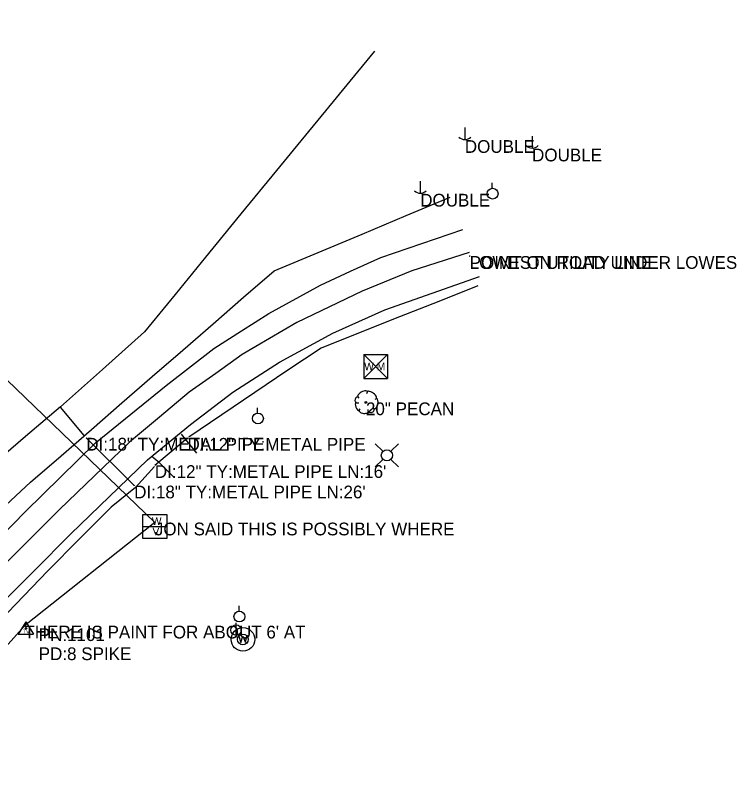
# Model space of a CAD drawing. Extents: x 1404740 to 1407214, y 1837339 to 1847120.
# Drawn here: x 1405945.4 to 1406228.7, y 1842443.8 to 1842749.5 of the extents above; entities that cross this region are included whole.
import ezdxf

# ---------------------------------------------------------------- set-up
doc = ezdxf.new("R2010")
doc.units = 0
for name, color, linetype in [('Ex_Major Contours', 7, 'Continuous'), ('S_DITCHLINE', 7, 'Continuous'), ('S_DRG_PT_SYM', 7, 'Continuous'), ('S_DRIVEWAY', 7, 'Continuous'), ('S_EDGE_PAVEMENT', 7, 'Continuous'), ('S_ELECTRIC_UTILITIES_ANNOT', 7, 'Continuous'), ('S_PAVEMENT_CROWN', 7, 'Continuous'), ('S_RDW_PT_SYM', 7, 'Continuous'), ('S_SIDE_DRAIN_ANNOT', 7, 'Continuous'), ('S_STREAM', 7, 'Continuous'), ('S_SURVEY_TEXT_ANNOT', 7, 'Continuous'), ('S_TREE', 7, 'Continuous'), ('S_TREE_ANNOT', 7, 'Continuous'), ('S_UTILITY_POLE', 7, 'Continuous'), ('S_UTILITY_POLE_ANNOT', 7, 'Continuous'), ('S_UTL_PT_SYM', 7, 'Continuous'), ('S_WATER_UTILITIES', 7, 'Continuous'), ('S_WATER_UTILITIES_ANNOT', 7, 'Continuous')]:
    doc.layers.add(name, color=color, linetype=linetype)

msp = doc.modelspace()

# ---------------------------------------------------------------- linework, layer by layer
at = {"layer": 'Ex_Major Contours'}
for p, q in [((1405991.98, 1842564.79), (1405973.17, 1842583.57)), ((1406000.11, 1842572.82), (1406012.93, 1842583.52))]:
    msp.add_line(p, q, dxfattribs=at)
at = {"layer": 'S_DITCHLINE'}
for points in [[(1406127.1, 1842643.3), (1406111.68, 1842637.19), (1406096.26, 1842631.07), (1406080.84, 1842624.96), (1406065.42, 1842618.85), (1406052.42, 1842610.1), (1406039.43, 1842601.35), (1406026.44, 1842592.61), (1406013.45, 1842583.86)], [(1405962.96, 1842595.61), (1405972.26, 1842584.46)], [(1406000.03, 1842572.3), (1405992.55, 1842564.07), (1405982.99, 1842556.38), (1405970.55, 1842543.87), (1405958.1, 1842531.36), (1405942.39, 1842514.95), (1405926.67, 1842498.54), (1405910.95, 1842482.13), (1405895.24, 1842465.71), (1405881.86, 1842451.53), (1405868.49, 1842437.35)]]:
    msp.add_lwpolyline(points, dxfattribs=at)
at = {"layer": 'S_DRG_PT_SYM'}
for points in [[(1405973.17, 1842583.57), (1405973.17, 1842583.62), (1405973.17, 1842583.57), (1405973.12, 1842583.57), (1405973.17, 1842583.57), (1405973.17, 1842583.52), (1405973.17, 1842583.57), (1405973.22, 1842583.57)], [(1406012.93, 1842583.52), (1406012.93, 1842583.57), (1406012.93, 1842583.52), (1406012.88, 1842583.52), (1406012.93, 1842583.52), (1406012.93, 1842583.47), (1406012.93, 1842583.52), (1406012.98, 1842583.52)], [(1406000.11, 1842572.82), (1406000.11, 1842572.87), (1406000.11, 1842572.82), (1406000.06, 1842572.82), (1406000.11, 1842572.82), (1406000.11, 1842572.77), (1406000.11, 1842572.82), (1406000.16, 1842572.82)], [(1405991.98, 1842564.79), (1405991.98, 1842564.84), (1405991.98, 1842564.79), (1405991.93, 1842564.79), (1405991.98, 1842564.79), (1405991.98, 1842564.74), (1405991.98, 1842564.79), (1405992.03, 1842564.79)]]:
    msp.add_lwpolyline(points, dxfattribs=at)
at = {"layer": 'S_DRIVEWAY'}
for p, q in [((1405949.47, 1842511.32), (1405946.46, 1842506.37)), ((1405949.47, 1842511.32), (1405952.42, 1842506.37)), ((1405946.46, 1842506.37), (1405952.42, 1842506.37))]:
    msp.add_line(p, q, dxfattribs=at)
for points in [[(1406010.41, 1842584.99), (1406012.18, 1842582.89), (1406016.54, 1842577.5)], [(1406007.64, 1842567.95), (1406001.75, 1842573.91), (1405999.22, 1842576.01)]]:
    msp.add_lwpolyline(points, dxfattribs=at)
for radius in [0.311, 0.183, 0.103]:
    msp.add_circle((1405949.47, 1842508.71), radius, dxfattribs=at)
at = {"layer": 'S_EDGE_PAVEMENT'}
for points in [[(1405825.85, 1842428.4), (1405841.19, 1842444.82), (1405850.15, 1842452.84), (1405856.44, 1842459.74), (1405871.87, 1842475.5), (1405887.3, 1842491.25), (1405903.15, 1842507.49), (1405919, 1842523.72), (1405934.15, 1842539.16), (1405949.29, 1842554.61), (1405963.06, 1842568.1), (1405976.82, 1842581.59), (1405990.68, 1842592.85), (1406004.54, 1842604.12), (1406023.33, 1842618.72), (1406034.11, 1842625.59), (1406044.9, 1842632.46), (1406065.21, 1842643.59), (1406077.05, 1842649.02), (1406088.89, 1842654.45), (1406104.99, 1842659.96), (1406121.09, 1842665.48)], [(1405864, 1842439.51), (1405878.64, 1842455.29), (1405893.11, 1842470.34), (1405907.58, 1842485.4), (1405922.75, 1842501), (1405937.92, 1842516.6), (1405952.51, 1842531.2), (1405967.11, 1842545.81), (1405982.2, 1842560.34), (1405997.29, 1842574.86), (1406014.16, 1842588.82), (1406030.8, 1842601.55), (1406049.08, 1842613.36), (1406070.04, 1842624.69), (1406090.47, 1842633.85), (1406109.07, 1842640.4), (1406127.67, 1842646.95)]]:
    msp.add_lwpolyline(points, dxfattribs=at)
at = {"layer": 'S_PAVEMENT_CROWN'}
msp.add_lwpolyline([(1406123.66, 1842656.34), (1406101.17, 1842649.25), (1406081.53, 1842641.18), (1406068.7, 1842635.01), (1406055.87, 1842628.84), (1406034.44, 1842616.3), (1406024.05, 1842608.9), (1406013.66, 1842601.51), (1406001.88, 1842591.71), (1405990.1, 1842581.9), (1405976.37, 1842568.67), (1405962.64, 1842555.44), (1405947.87, 1842540.59), (1405933.09, 1842525.75), (1405918.78, 1842510.91), (1405904.46, 1842496.07), (1405890.02, 1842480.85), (1405875.57, 1842465.64), (1405861.34, 1842450.66), (1405847.12, 1842435.69)], dxfattribs=at)
at = {"layer": 'S_RDW_PT_SYM'}
msp.add_lwpolyline([(1406123.85, 1842654.98), (1406123.85, 1842655.03), (1406123.85, 1842654.98), (1406123.8, 1842654.98), (1406123.85, 1842654.98), (1406123.85, 1842654.93), (1406123.85, 1842654.98), (1406123.9, 1842654.98)], dxfattribs=at)
at = {"layer": 'S_STREAM'}
msp.add_lwpolyline([(1406086.45, 1842735.46), (1406076.8, 1842723.75), (1406067.15, 1842712.04), (1406057.5, 1842700.33), (1406047.86, 1842688.62), (1406033.92, 1842671.61), (1406019.99, 1842654.6), (1406008.04, 1842639.91), (1405996.1, 1842625.22), (1405979.54, 1842610.47), (1405962.98, 1842595.73), (1405949.29, 1842584.1), (1405935.6, 1842572.46)], dxfattribs=at)
at = {"layer": 'S_TREE'}
for p, q in [((1406079.83, 1842599.7), (1406080.33, 1842599.12)), ((1406083.62, 1842601.72), (1406083.24, 1842600.86)), ((1406079.17, 1842597.38), (1406080.29, 1842597.38)), ((1406087.19, 1842598.93), (1406086.53, 1842598.66)), ((1406080.33, 1842594.2), (1406080.8, 1842594.9)), ((1406084.01, 1842593.93), (1406083.93, 1842594.7)), ((1406086.41, 1842594.82), (1406085.95, 1842595.25))]:
    msp.add_line(p, q, dxfattribs=at)
msp.add_lwpolyline([(1405941.54, 1842557.14), (1405951.29, 1842566.15), (1405963.25, 1842576.52), (1405975.21, 1842586.9), (1405987.17, 1842597.28), (1405999.12, 1842607.66), (1406011.08, 1842618.04), (1406023.04, 1842628.41), (1406035, 1842638.79), (1406046.96, 1842649.17), (1406064.27, 1842656.41), (1406081.58, 1842663.65), (1406098.9, 1842670.89), (1406116.21, 1842678.12)], dxfattribs=at)
msp.add_circle((1406083.07, 1842597.47), 0.341, dxfattribs=at)
for centre, major_axis, ratio, start_param, end_param in [((1406081.73, 1842600.67), (1.86, 1.08), 0.471018, 0, 3.141593), ((1406085.39, 1842600.35), (-1.81, 1.36), 0.405113, 3.141593, 6.283186), ((1406079.5, 1842598.56), (0.31, 1.03), 0.646762, 0, 3.141593), ((1406086.74, 1842596.94), (0.46, 2.04), 0.482994, 3.141593, 6.283185), ((1406079.8, 1842595.91), (-0.61, 1.6), 0.420543, 6.283185, 9.424777), ((1406082.26, 1842594.13), (-1.83, 0.19), 0.529943, 0, 3.141593), ((1406085.22, 1842594.42), (1.09, 0.46), 0.711534, 3.141592, 6.283185)]:
    msp.add_ellipse(centre, major_axis=major_axis, ratio=ratio, start_param=start_param, end_param=end_param, dxfattribs=at)
at = {"layer": 'S_UTILITY_POLE'}
for p, q in [((1406121.91, 1842705.5), (1406121.91, 1842700.77)), ((1406148.33, 1842702.16), (1406148.33, 1842697.43)), ((1406104.39, 1842684.4), (1406104.39, 1842679.67)), ((1406132.71, 1842681.66), (1406132.71, 1842683.77)), ((1406040.5, 1842593.31), (1406040.5, 1842595.42)), ((1406089.69, 1842578.27), (1406086.71, 1842581.25)), ((1406092.87, 1842578.27), (1406095.85, 1842581.25)), ((1406089.69, 1842575.09), (1406086.71, 1842572.11)), ((1406092.87, 1842575.09), (1406095.85, 1842572.11)), ((1406033.2, 1842515.47), (1406033.2, 1842517.58)), ((1406032.05, 1842505.08), (1406032.05, 1842510.87))]:
    msp.add_line(p, q, dxfattribs=at)
for centre, radius in [((1406132.84, 1842679.52), 2.13), ((1406040.62, 1842591.17), 2.13), ((1406091.29, 1842576.69), 2.21), ((1406033.33, 1842513.33), 2.13), ((1406032.05, 1842508.01), 2.05)]:
    msp.add_circle(centre, radius, dxfattribs=at)
for centre in [(1406121.97, 1842704.2), (1406148.4, 1842700.86), (1406104.45, 1842683.1)]:
    msp.add_arc(centre, 3.41, 226.3972, 313.6028, dxfattribs=at)
at = {"layer": 'S_UTL_PT_SYM'}
for points in [[(1406123.85, 1842654.98), (1406123.85, 1842655.03), (1406123.85, 1842654.98), (1406123.8, 1842654.98), (1406123.85, 1842654.98), (1406123.85, 1842654.93), (1406123.85, 1842654.98), (1406123.9, 1842654.98)], [(1406000.11, 1842550.24), (1406000.11, 1842550.29), (1406000.11, 1842550.24), (1406000.06, 1842550.24), (1406000.11, 1842550.24), (1406000.11, 1842550.19), (1406000.11, 1842550.24), (1406000.16, 1842550.24)], [(1405948.84, 1842509.73), (1405948.84, 1842509.78), (1405948.84, 1842509.73), (1405948.79, 1842509.73), (1405948.84, 1842509.73), (1405948.84, 1842509.68), (1405948.84, 1842509.73), (1405948.89, 1842509.73)]]:
    msp.add_lwpolyline(points, dxfattribs=at)
at = {"layer": 'S_WATER_UTILITIES'}
for p, q in [((1405793.44, 1842749.52), (1406000.11, 1842550.24)), ((1406082.2, 1842616.34), (1406091.54, 1842616.34)), ((1406082.2, 1842616.34), (1406082.2, 1842606.84)), ((1406082.2, 1842616.34), (1406091.54, 1842606.84)), ((1406091.54, 1842616.34), (1406082.2, 1842606.84)), ((1406091.54, 1842616.34), (1406091.54, 1842606.84)), ((1406082.2, 1842606.84), (1406091.54, 1842606.84)), ((1405995.4, 1842553.44), (1406004.81, 1842553.44)), ((1405995.4, 1842544.03), (1405995.4, 1842553.44)), ((1406004.81, 1842553.44), (1406004.81, 1842544.03)), ((1406000.11, 1842550.24), (1405948.84, 1842509.73)), ((1405995.4, 1842548.75), (1406004.81, 1842548.75)), ((1406004.81, 1842544.03), (1405995.4, 1842544.03)), ((1405948.84, 1842509.73), (1405767.47, 1842305.82)), ((1406033.18, 1842505.6), (1406033.84, 1842503.12)), ((1406033.84, 1842503.12), (1406034.65, 1842505.6)), ((1406034.65, 1842505.6), (1406035.7, 1842503.12)), ((1406035.7, 1842503.12), (1406036.28, 1842505.64))]:
    msp.add_line(p, q, dxfattribs=at)
for centre, radius in [((1406034.74, 1842504.34), 4.63), ((1406034.71, 1842504.34), 2.13)]:
    msp.add_circle(centre, radius, dxfattribs=at)

# ---------------------------------------------------------------- texts
at = {"layer": 'S_DRIVEWAY'}
msp.add_text('TV', height=1.5, rotation=360, dxfattribs=at).set_placement((1405948.27, 1842506.7))
at = {"layer": 'S_ELECTRIC_UTILITIES_ANNOT'}
msp.add_text('LOWEST UTILITY LINE', height=5, dxfattribs=at).set_placement((1406123.85, 1842649.98))
at = {"layer": 'S_SIDE_DRAIN_ANNOT'}
for s, p in [('DI:18" TY:METAL PIPE', (1405973.17, 1842578.57)), ('DI:12" TY:METAL PIPE', (1406012.93, 1842578.52)), ('DI:12" TY:METAL PIPE LN:16\'', (1406000.11, 1842567.82)), ('DI:18" TY:METAL PIPE LN:26\'', (1405991.98, 1842559.79))]:
    msp.add_text(s, height=5, dxfattribs=at).set_placement(p)
at = {"layer": 'S_STREAM'}
for s, p in [('PN:1101', (1405954.47, 1842503.71)), ('PD:8 SPIKE', (1405954.47, 1842496.21))]:
    msp.add_text(s, height=5, dxfattribs=at).set_placement(p)
at = {"layer": 'S_SURVEY_TEXT_ANNOT'}
msp.add_text('POINT ON ROAD UNDER LOWES', height=5, dxfattribs=at).set_placement((1406123.85, 1842649.98))
at = {"layer": 'S_TREE_ANNOT'}
msp.add_text('20" PECAN', height=5, dxfattribs=at).set_placement((1406083.07, 1842592.47))
at = {"layer": 'S_UTILITY_POLE_ANNOT'}
for p in [(1406121.93, 1842695.56), (1406148.35, 1842692.22), (1406104.4, 1842674.46)]:
    msp.add_text('DOUBLE', height=5, dxfattribs=at).set_placement(p)
at = {"layer": 'S_WATER_UTILITIES'}
for s, p in [('W M', (1406082.41, 1842610.1)), ('W', (1405998.95, 1842549.29)), ('V', (1405999.18, 1842545.22))]:
    msp.add_text(s, height=3, rotation=360, dxfattribs=at).set_placement(p)
at = {"layer": 'S_WATER_UTILITIES_ANNOT'}
for s, p in [('JON SAID THIS IS POSSIBLY WHERE', (1406000.11, 1842545.24)), ("THERE IS PAINT FOR ABOUT 6' AT ", (1405948.84, 1842504.73))]:
    msp.add_text(s, height=5, dxfattribs=at).set_placement(p)

doc.saveas('drawing.dxf')
